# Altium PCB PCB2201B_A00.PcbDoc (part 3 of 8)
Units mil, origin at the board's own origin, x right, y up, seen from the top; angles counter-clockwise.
Board outline 4523.63 x 2358.23 mil, 6 copper layers (Top Layer, Signal Layer 2, Signal Layer 3, Signal Layer 4, Signal Layer 5, Bottom Layer), stack 61.221 mil thick; 383 components, 308 nets, 1386 pads, 1147 vias.
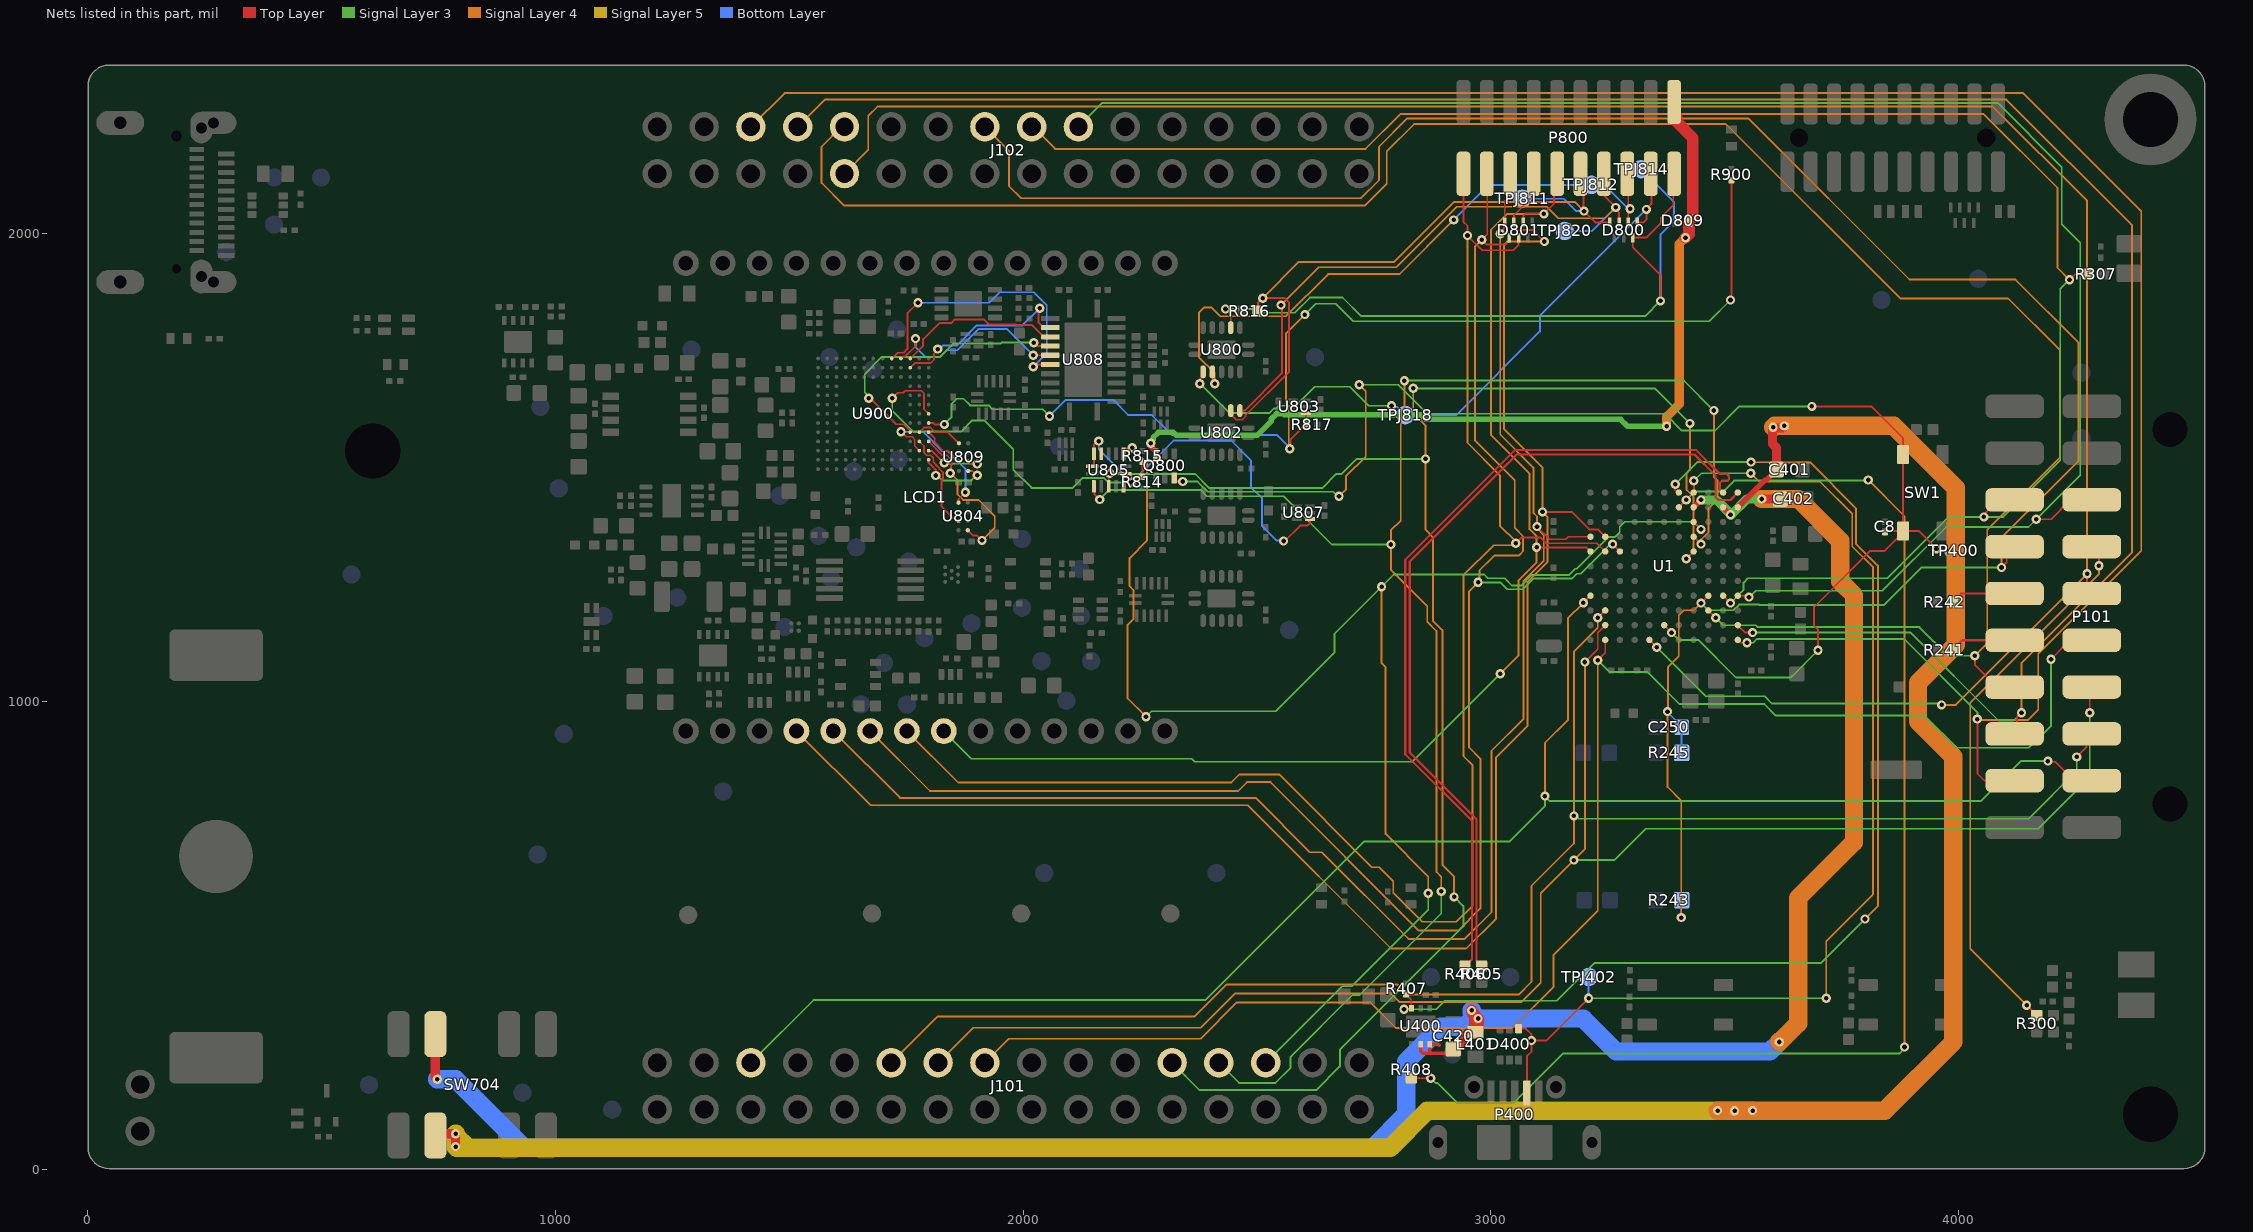
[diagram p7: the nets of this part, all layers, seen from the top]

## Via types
v1: diameter 19.68, hole 9.84, Top Layer to Bottom Layer, tented both sides, 768 vias
v2: diameter 20, hole 9.84, Top Layer to Bottom Layer, tented both sides, 379 vias

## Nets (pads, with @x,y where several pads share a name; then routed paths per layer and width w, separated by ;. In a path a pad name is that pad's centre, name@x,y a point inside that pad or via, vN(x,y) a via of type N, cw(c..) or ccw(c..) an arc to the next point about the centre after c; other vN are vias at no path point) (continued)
DEBUG_#RESET_C2CKPS: C8.1 Q800.6 SW1.1 SW1.2 TP400.1 U1.K6 | length 3010.6
  Top Layer w3.94: Q800.6@2322.83,1478.35 2322.83,1474.41 2326.77,1470.47 v2(2341.54,1470.47) ; U1.K6@3370.08,1163.39 v1(3385.85,1147.59) ; v1(3685.75,1630.98) 3812.59,1630.98 3880.58,1562.99 SW1.2@3880.58,1528.1 SW1.1@3880.58,1364.71 ; v1(3698.86,1109.76) 3698.86,1154.06 3690.35,1162.56 3690.35,1202.17 3810.2,1322.01 3841.16,1322.01 SW1.1@3881.93,1362.77 ; C8.1@3842.56,1362.77 3844.5,1364.71 SW1.1@3880.58,1364.71 ; SW1.1@3883.09,1362.2 SW1.1@3880.58,1364.71 ; v1(3952.2,1326.61) 3914.1,1364.71 3881.93,1364.71 SW1.1@3880.58,1364.71
  Signal Layer 3 w3.94: v2(2341.54,1470.47) 2372.5,1470.47 2394.38,1448.6 2662.55,1448.6 2672.17,1438.98 v1(2675.2,1438.98) ; v1@2718.94,1677.17 2802.06,1677.17 2864.06,1615.16 3372.05,1615.16 3408.03,1579.18 3478.78,1579.18 3530.59,1630.98 v1(3685.75,1630.98) ; v1(3385.85,1147.59) 3401.6,1131.85 3442.96,1131.85 3523.62,1051.18 3524.06,1051.62 3641.28,1051.62 3643.58,1053.92 3643.58,1054.49 v1(3698.86,1109.76)
  Signal Layer 4 w3.94: v1(2675.2,1438.98) 2690.37,1454.15 2690.37,1458.45 2690,1458.82 2690,1481.34 2732.28,1523.62 2732.28,1663.39 v1(2718.5,1677.17)
  Bottom Layer w3.94: v1(3952.2,1326.61) 3954.11,1324.71 3986.74,1324.71 TP400.1@3988.65,1322.8
DEBUG_#RESET_IN: U808.7 U900.N5 | length 628.1
  Top Layer w3.94: U900.N5@1719.49,1733.27 1731.93,1745.71 1744.93,1745.71 1752.95,1753.73 1752.95,1829.72 v2(1775.59,1852.36) ; v2(2021.65,1715.55) 2026,1715.55 2030.92,1720.47 U808.7@2058.27,1720.47
  Bottom Layer w3.94: v2(1775.59,1852.36) 1928.15,1852.36 1950.54,1874.75 2023,1874.75 2050.86,1846.89 2050.86,1744.75 v2(2021.65,1715.55)
DEBUG_DH_SW_ENABLE: R817.2 R900.1 U803.4 U900.F1 | length 2494.9
  Top Layer w3.94: U900.F1@1798.23,1595.47 1808.52,1595.47 1811.47,1592.52 v1(1832.06,1592.52) ; v2(2570.12,1540.35) 2571.85,1542.09 2571.85,1560.48 2595.96,1584.58 2597.33,1584.58 2604.73,1591.98 R817.2@2605.13,1591.98 2605.13,1615.34 U803.4@2604.33,1616.14 ; v1(3511.92,1858.27) 3513.78,1860.13 R900.1@3513.78,2114.17
  Signal Layer 3 w3.94: v1(1832.06,1592.52) 1846.91,1607.37 1846.91,1635.52 1858.75,1647.36 1872.79,1647.36 1887.02,1633.13 1926.38,1633.13 1934.65,1624.85 2041.91,1624.85 v2(2056.53,1610.24) ; v1(2602.36,1827.05) 2625.7,1850.39 2668.39,1850.39 2705.79,1812.99 3466.65,1812.99 v1(3511.92,1858.27)
  Signal Layer 4 w3.94: 2562.01,1652.59 2562.01,1637.8 2567.77,1632.03 2567.77,1542.7 v2(2570.12,1540.35) ; 2562.03,1652.61 2562.03,1667.37 2561.87,1667.53 2561.87,1786.56 v1(2602.36,1827.05)
  Bottom Layer w3.94: v2(2056.53,1610.24) 2090.98,1644.69 2192.38,1644.69 2224.58,1612.48 2275.31,1612.48 2317.91,1569.88 2542.32,1569.88 2570.12,1542.09 v2(2570.12,1540.35)
DEBUG_MCU_SW_ENABLE: R814.2 R815.2 U805.5 U805.6 U805.12 U805.13 U807.4 U900.G1 | length 1685.9
  Top Layer w3.94: v2(1720.47,1648.62) 1732,1660.15 1743.92,1660.15 1748.14,1664.37 1782.62,1664.37 1788.39,1658.6 1788.39,1625 U900.G1@1798.23,1615.16 ; U805.13@2148.23,1502.76 2149.61,1502.76 2151.57,1504.72 2151.57,1548.6 2159.82,1556.84 v2(2161.7,1556.84) ; U805.5@2214.57,1460.04 2214.57,1485.04 2216.54,1487.01 2227.36,1487.01 2229.78,1484.59 2229.98,1484.59 2232.28,1482.28 v2(2232.28,1468.5) 2244.11,1480.33 R814.2@2254.09,1480.33 ; R814.2@2254.92,1480.33 R815.2@2254.92,1512.03 ; v1(2556.85,1343.27) 2559.49,1343.27 2592.29,1376.07 2607.27,1376.07 2613.38,1382.17 U807.4@2613.38,1390.14
  Signal Layer 3 w3.94: v2(1720.47,1648.62) 1720.47,1621.83 1765.09,1577.21 1867.65,1577.21 1891.54,1601.1 1916.84,1601.1 1979.05,1538.89 1979.05,1495.87 2018.27,1456.65 2105.88,1456.65 2127.29,1478.07 2172.83,1478.07 2182.4,1468.5 v2(2232.28,1468.5)
  Bottom Layer w3.94: v2(2161.7,1556.84) 2161.7,1539.09 v2(2232.28,1468.5) 2321.77,1557.99 2444.88,1557.99 2486.92,1515.95 2486.92,1458.19 2510.79,1434.33 2510.79,1374.95 2541.1,1344.64 2555.48,1344.64 v1(2556.85,1343.27)
DEBUG_RESET_#OE: U804.A1 U900.D1 | length 347.2
  Top Layer w3.94: U900.D1@1799.48,1555.84 1799.48,1554.85 1827.78,1526.55 1837.53,1526.55 1847,1517.08 1847,1504.26 1845.97,1503.22 1845.97,1489.53 v2(1844.63,1488.19) ; U804.A1@1881.89,1366.14 1893.23,1354.8 1902.04,1354.8 1912.35,1344.49 v2(1912.4,1344.49)
  Signal Layer 4 w3.94: v2(1844.63,1488.19) 1860.23,1472.6 1860.23,1442.64 1871.97,1430.9 1904.95,1430.9 1939.68,1396.17 1939.68,1371.77 v2(1912.4,1344.49)
DEBUG_TCK_SWCLK_#OE: U809.A1 U900.B1 | length 161.3
  Top Layer w3.94: U900.B1@1798.23,1516.73 1798.37,1516.59 1798.37,1510.83 1813.7,1495.5 v2(1813.7,1483.18) ; U809.A1@1882.87,1493.11 1891.73,1493.11 1901.02,1483.83 v2(1902.13,1483.83)
  Signal Layer 3 w3.94: v2(1813.7,1483.18) 1813.7,1481.72 1818.04,1481.72 1827.03,1472.73 1889.62,1472.73 1900.16,1483.27 1901.57,1483.27 v2(1902.13,1483.83)
DEBUG_TCK_SWCLK_C2CK: J101.24 U1.E8 U805.3 | length 3693.5
  Top Layer w3.94: U805.3@2183.07,1460.04 2183.07,1486.22 v2(2185.04,1488.19) ; v1@3419.3,1307.09 U1.E8@3433.07,1320.87
  Signal Layer 3 w3.94: v2(2185.04,1488.19) 2186.73,1486.5 2367.61,1486.5 2397.64,1456.47 2639.19,1456.47 2669.41,1486.7 2681.15,1486.7 2713.11,1518.66 v1(2860.16,1518.66) ; J101.24@2318.5,228.43 2377.12,169.81 2626.51,169.81 2677.17,220.47 2677.17,255.91 2940.94,519.69 2940.94,562.99 v1(2921.26,582.68) ; v1(2833.97,1669.5) 3350.18,1669.5 v1(3425.2,1594.49)
  Signal Layer 4 w3.94: v1(2833.97,1669.5) 2833.97,1615.83 2860.16,1589.65 2860.16,1367.2 2875.98,1351.38 2875.98,1173.23 2896.19,1153.03 2896.19,651.06 2921.26,625.98 v1(2921.26,582.68) ; v1@3419.3,1307.09 3433.07,1320.86 3433.07,1437.01 3432.85,1437.23 3432.85,1437.51 3418.07,1452.3 3418.07,1488.19 3425.2,1495.32 v1(3425.2,1594.49)
  other v1: 3417.32,1305.12
DEBUG_TCK_SWCLK_IN: U808.4 U900.N3 | length 357.5
  Top Layer w3.94: U900.N3@1758.86,1733.27 1786.42,1760.83 1786.42,1774.61 1820.87,1809.06 1846.46,1809.06 1854.14,1816.74 1915.76,1816.74 1926.4,1806.1 1984.56,1806.1 1985.54,1805.12 2018.7,1805.12 2044.29,1779.53 U808.4@2058.27,1779.53
DEBUG_TCK_SWCLK_OUT: U809.B1 U900.C1 | length 140.5
  Top Layer w3.94: U900.C1@1798.23,1536.42 1798.98,1535.66 1804.89,1535.66 1830.5,1510.05 1831.11,1510.67 v2(1831.54,1510.67) ; U809.B1@1882.87,1512.8 1887.8,1507.87 v2(1902.56,1507.87)
  Signal Layer 3 w3.94: v2(1831.54,1510.67) 1830.5,1509.63 1831.38,1508.75 1901.68,1508.75 v2(1902.56,1507.87)
DEBUG_TDI_#OE: U809.B2 U900.E1 | length 96.1
  Top Layer w3.94: U900.E1@1798.23,1575.79 1811.3,1562.71 1811.3,1554.16 1830.03,1535.43 1840.55,1535.43 U809.B2@1863.19,1512.8
DEBUG_TDI_C2DPS: U805.11
DEBUG_TDI_IN: U808.6 U900.N4 | length 420.9
  Top Layer w3.94: U900.N4@1739.17,1733.27 1740.24,1733.27 1744.81,1737.84 1748.19,1737.84 1770.33,1759.98 v2(1770.33,1775.87) ; v2(2021.65,1740.16) U808.6@2058.27,1740.16
  Bottom Layer w3.94: v2(1770.33,1775.87) 1770.33,1757.23 1790.92,1736.64 1822.71,1736.64 1837.06,1750.98 1859.56,1750.98 1904.57,1795.99 1965.82,1795.99 v2(2021.65,1740.16)
DEBUG_TDI_OUT: U809.D2 U900.E2 | length 102.6
  Top Layer w3.94: U900.E2@1778.54,1575.79 1788.39,1585.63 1802.31,1585.63 1812.15,1575.79 1839.42,1575.79 1863.04,1552.17 U809.D2@1863.19,1552.17
DEBUG_TDO_SWO: J101.28 U1.C8 U805.8 | length 3309.6
  Top Layer w3.94: U805.8@2214.57,1529.72 2214.57,1538.39 2216.54,1540.35 2216.54,1541.14 2232.09,1541.14 v2(2233.27,1542.32) ; U1.C8@3433.07,1383.86 v1(3448.85,1368.09)
  Signal Layer 3 w3.94: v1(2262.8,967.52) 2274.61,979.33 2540.35,979.33 2665.35,1104.33 2665.35,1144.57 2792.44,1271.65 2985.24,1271.65 2993.11,1263.78 3029.22,1263.78 3044.97,1248.03 3064.65,1248.03 3087.4,1270.78 3167.43,1270.78 3180.56,1283.9 3183.51,1283.9 3251.51,1351.91 3265.35,1351.91 3275.2,1361.76 3275.2,1373.69 3285.79,1384.28 3432.66,1384.28 v1(3448.85,1368.09) ; J101.28@2518.5,228.43 2681.81,391.73 2702.76,391.73 2866.14,555.12 v1(2866.14,590.55)
  Signal Layer 4 w3.94: v2(2233.27,1542.32) 2264.76,1510.83 2264.76,1343.83 2227.64,1306.71 2227.64,1246.85 2235.94,1238.56 2235.94,1176.25 2223.58,1163.89 2223.58,1006.74 2261.81,968.5 v1@2261.81,967.52 ; v1(2766.26,1245.47) 2766.26,1082.13 2774.76,1073.62 2774.76,717.36 2866.14,625.98 v1(2866.14,590.55)
DEBUG_TDO_SWO_IN: U808.5 U900.E3 | length 603.6
  Top Layer w3.94: v2(1670.28,1648.62) 1673.45,1648.62 1729.27,1592.8 1745.2,1592.8 1754.74,1583.26 1758.11,1579.89 1758.11,1576.54 U900.E3@1758.86,1575.79 ; v2(2022.64,1766.73) 2025.98,1766.73 2032.87,1759.84 U808.5@2058.27,1759.84
  Signal Layer 3 w3.94: v2(1670.28,1648.62) 1670.28,1652.97 1661.7,1661.55 1661.7,1700.08 1698.25,1736.64 1822.71,1736.64 1851.12,1765.05 1951.8,1765.05 1954.55,1767.81 2021.56,1767.81 v2(2022.64,1766.73)
DEBUG_TMS_SWDIO_#OE: U804.B2 U900.D2 | length 215.3
  Top Layer w3.94: U900.D2@1778.54,1556.1 1788.39,1546.26 1788.39,1532.34 1794.15,1526.57 1802.31,1526.57 1808.07,1520.81 1808.07,1512.26 1815.94,1504.39 1821.57,1498.76 1821.57,1497.19 1829.17,1489.59 1829.17,1488.12 1829.17,1475.31 1826.07,1472.21 1826.07,1416.82 1856.19,1386.69 1861.34,1386.69 U804.B2@1862.2,1385.83
DEBUG_TMS_SWDIO_C2D: J101.26 U1.D8 U805.1 | length 3578.5
  Top Layer w3.94: U805.1@2151.57,1460.04 2152.45,1459.17 2152.45,1443.57 v2(2164.21,1431.81) ; U1.D8@3433.07,1352.36 v1(3448.85,1336.59)
  Signal Layer 3 w3.94: v2(2164.21,1431.81) 2164.21,1432.67 2184.01,1452.48 2379.36,1452.48 2392.86,1438.98 2556.81,1438.98 2659.96,1335.83 v1(2786.1,1335.83) ; J101.26@2418.5,228.43 2461.89,185.04 2539.37,185.04 2571.85,217.52 2571.85,241.14 2703.74,373.03 2719.49,373.03 2893.7,547.24 v1(2893.7,594.49) ; v1(2814.96,1685.91) 3412.51,1685.91 v1(3476.38,1622.05)
  Signal Layer 4 w3.94: v1(2814.96,1685.91) 2814.96,1614.17 2807.09,1606.3 2807.09,1386.81 2786.1,1365.83 v1(2786.1,1335.83) 2786.1,1281.61 2863.7,1204.02 2863.7,1170.71 2883.62,1150.79 2883.62,636.07 2893.7,625.98 v1(2893.7,594.49) ; v1(3448.85,1336.59) 3448.85,1346.17 3465.04,1362.36 3465.04,1413.68 3484.25,1432.89 3484.25,1472.32 3476.38,1480.19 v1(3476.38,1622.05)
DEBUG_TMS_SWDIO_IN: U808.3 U900.M3 | length 398.7
  Top Layer w3.94: U900.M3@1758.86,1713.58 1768.7,1723.43 1802.31,1723.43 1809.73,1730.85 1809.73,1743.1 1817.64,1751.01 v2(1817.64,1753.44) ; v2(2035.39,1840.49) 2032.87,1837.97 2032.87,1810.63 2044.29,1799.21 U808.3@2058.27,1799.21
  Bottom Layer w3.94: v2(1817.64,1753.44) 1820.67,1753.44 1828.06,1760.83 1858.27,1760.83 1901.3,1803.86 1998.77,1803.86 v2(2035.39,1840.49)
DEBUG_TMS_SWDIO_OUT: U804.D2 U900.C2 | length 308.4
  Top Layer w3.94: v2@1743.11,1573.82 1743.11,1573.69 1750.86,1565.94 1762.94,1565.94 1768.7,1560.18 1768.7,1546.26 U900.C2@1778.54,1536.42 ; U804.D2@1862.2,1425.2 1862.2,1433.07 v2(1876.94,1447.81)
  Bottom Layer w3.94: v2(1739.27,1576.85) 1786.34,1576.85 1827.76,1535.43 1839.57,1535.43 1876.94,1498.06 v2(1876.94,1447.81)
DEBUG_TRACECLK: D801.2 LCD1.8 P800.12 U1.E1 | length 2713.3
  Top Layer w3.94: D801.2@3068.9,2024.21 3069.09,2024.4 3069.09,2038.24 3074.16,2043.31 3114.17,2043.31 3134.68,2063.82 3134.68,2118.6 P800.12@3139.62,2123.53 ; v1(3097.44,1329.72) 3203.74,1329.72 U1.E1@3212.6,1320.87
  Signal Layer 3 w3.94: LCD1.8@1830.71,937.01 1889.76,877.95 2360.55,877.95 2367,871.5 2831.69,871.5 v1(3019.68,1059.49)
  Signal Layer 4 w3.94: v1(3019.68,1059.49) 3059.06,1098.86 3059.06,1259.17 3097.44,1297.55 v1(3097.44,1329.72) 3097.44,1353.35 3082.68,1368.11 3082.68,1487.2 3000,1569.88 3000,2007.87 3034.45,2042.32 v1(3113.19,2042.32)
DEBUG_TRACED0: D801.3 LCD1.4 P800.14 U1.D2 | length 3679
  Top Layer w3.94: D801.3@3049.21,2024.21 3049.21,2039.64 3091.14,2081.57 P800.14@3091.14,2124.72 ; D801.3@3050.2,2016.54 3058.86,2007.87 3089.57,2007.87 v1(3114.17,1983.27) ; v1(3110.24,1405.51) 3172.72,1405.51 3210.13,1368.09 3228.36,1368.09 U1.D2@3244.09,1352.36
  Signal Layer 4 w3.94: LCD1.4@1515.75,937.01 1674.21,778.54 2480.32,778.54 2786.42,472.44 2946.85,472.44 3010.83,536.42 3010.83,880.91 3077.76,947.83 3077.76,1254.92 3120.63,1297.79 3120.63,1395.12 v1(3110.24,1405.51) 3110.24,1500 3027.56,1582.68 3027.56,1976.38 3034.45,1983.27 v1(3114.17,1983.27)
DEBUG_TRACED1: D801.4 LCD1.5 P800.16 U1.D1 | length 3395
  Top Layer w3.94: v1@3016.73,2000 3028.13,2011.4 3028.13,2022.81 D801.4@3029.53,2024.21 3029.53,2069.56 3044.29,2084.32 P800.16@3044.29,2107.28 ; v1(3098.43,1374.02) 3125.55,1346.89 3160.15,1346.89 3165.62,1352.36 U1.D1@3212.6,1352.36
  Signal Layer 4 w3.94: LCD1.5@1594.49,937.01 1737.2,794.29 2497.05,794.29 2613.19,678.15 2638.78,678.15 2823.82,493.11 2943.9,493.11 3001.11,550.32 3001.11,894.81 3069.88,963.58 3069.88,1258.18 3112.75,1301.05 3112.75,1355.86 3098.43,1370.19 3098.43,1395.67 3090.55,1403.54 3090.55,1500 3019.68,1570.87 v1(3019.68,2000)
DEBUG_TRACED2: D801.5 LCD1.6 P800.18 U1.E3 | length 3649.5
  Top Layer w3.94: P800.18@2991.14,2124.72 2992.13,2123.74 2992.13,1999.02 v1(2980.32,1987.2) 2990.9,1976.62 3030.76,1976.62 3037.2,1983.07 3037.6,1983.07 3040.55,1986.02 D801.5@3040.55,1986.42 ; v1(3259.85,1336.59) U1.E3@3275.59,1320.87
  Signal Layer 3 w3.94: v1(2972.44,1254.92) 3020.29,1254.92 3035.06,1240.16 3067.91,1240.16 3090.66,1262.91 3172.79,1262.91 3183.07,1273.19 3191.49,1273.19 3254.9,1336.59 v1(3259.85,1336.59)
  Signal Layer 4 w3.94: LCD1.6@1673.23,937.01 1801.18,809.06 2459.65,809.06 2478.89,828.3 2528.63,828.3 2846.1,510.83 2930.12,510.83 2977.36,558.07 2977.36,877.76 2953.19,901.93 2953.19,1235.67 v1(2972.44,1254.92) 2975.15,1257.63 2975.15,1280.27 3006.89,1312.01 3059.06,1312.01 3068.46,1321.41 3068.46,1353.47 3050.74,1371.19 3050.74,1472.88 2965.99,1557.63 2965.99,1972.88 v1(2980.32,1987.2)
DEBUG_TRACED3: D801.6 LCD1.7 P800.20 U1.E2 | length 3458
  Top Layer w3.94: P800.20@2941.14,2124.72 2941.14,2025.39 2949.8,2016.73 v1(2949.8,1996.06) 2981.3,1964.57 3047.24,1964.57 3059.06,1976.38 D801.6@3059.06,1991.54 ; v1(3053.15,1338.58) 3064.96,1350.39 3106.3,1350.39 3118.11,1338.58 3226.38,1338.58 U1.E2@3244.09,1320.87
  Signal Layer 4 w3.94: LCD1.7@1751.97,937.01 1861.77,827.21 2445.32,827.21 2462.6,844.49 2547.24,844.49 2745.57,646.16 2761.32,646.16 2791.34,616.14 2791.34,591.54 2853.35,529.53 2926.18,529.53 2960.63,563.98 2960.63,864.17 2940.94,883.86 2940.94,1269.69 3005.49,1334.23 3048.8,1334.23 v1(3053.15,1338.58) 3053.15,1342.41 3019.25,1376.31 3019.25,1483.7 2949.8,1553.15 v1(2949.8,1996.06)
DH_#RESET: D800.4 P800.10 R816.1 TPJ811.1 U802.3 | length 1490.3
  Top Layer w3.94: U802.3@2443.9,1622.05 2443.9,1614.17 2455.71,1602.36 2468.47,1602.36 2475.39,1609.28 2475.39,1612.2 2568.46,1705.27 2568.46,1852.8 2559.05,1862.2 2558.07,1862.2 2557.56,1862.72 2512.62,1862.72 v1(2512.11,1862.2) ; R816.1@2500.98,1834.65 2501.97,1835.63 2501.97,1852.36 v1@2511.81,1862.2 ; P800.10@3189.62,2125.5 3197.72,2117.4 3197.72,2049.33 v1(3198.82,2048.23) 3222.83,2024.21 D800.4@3253.94,2024.21
  Signal Layer 4 w3.94: v1(2512.11,1862.2) 2589.51,1939.61 2792.95,1939.61 2921.26,2067.91 3179.13,2067.91 v1(3198.82,2048.23)
  Bottom Layer w3.94: TPJ811.1@3067.71,2074.8 3155.51,2074.8 3182.09,2048.23 v1(3198.82,2048.23)
DH_TCK_SWCLK: D800.1 P800.4 TPJ818.1 U800.9 | length 1378.4
  Top Layer w3.94: v2(2377.95,1679.13) 2377.95,1688.98 2384.84,1695.87 U800.9@2384.84,1704.72 ; D800.1@3314.76,2023.62 3325.79,2023.62 3332.13,2029.96 3332.13,2052.92 3342.77,2063.56 3342.77,2123.3 P800.4@3341.34,2124.72
  Signal Layer 3 w3.94: v2(2377.95,1679.13) 2379.16,1679.13 2441.81,1616.48 2526.3,1616.48 2536.35,1626.53 2540.93,1626.53 2546.84,1632.44 2583.22,1632.44 2623.58,1672.79 2698.27,1672.79 2738.63,1632.44 v1(2787.4,1632.44)
  Bottom Layer w3.94: v1(2787.4,1632.44) 2789.54,1630.3 2798.83,1630.3 TPJ818.1@2816.93,1612.2 2852.36,1612.2 2925.71,1612.2 3104.65,1791.14 3104.65,1824.45 v1(3332.13,2051.93)
DH_TDI: D800.3 P800.8 TPJ820.1 U802.2 | length 1336.2
  Top Layer w3.94: U802.2@2463.58,1622.05 2473.65,1622.05 2553.15,1701.55 2553.15,1846.46 2552.17,1846.46 v1(2551.22,1847.41) ; P800.8@3241.14,2124.72 3241.14,2081.69 v1(3266.73,2056.1) 3266.73,2051.84 3273.62,2044.95 D800.3@3273.62,2024.21
  Signal Layer 4 w3.94: v1(2551.22,1847.41) 2632.08,1928.27 2797.36,1928.27 2926.73,2057.63 3119.53,2057.63 3144.25,2032.92 3243.55,2032.92 v1(3266.73,2056.1)
  Bottom Layer w3.94: TPJ820.1@3157.48,2005.91 3216.54,2005.91 v1(3266.73,2056.1)
DH_TDO_SWO: D800.2 P800.6 TPJ812.1 U800.10 | length 1379.7
  Top Layer w3.94: v2@2404.53,1682.09 2406.37,1683.93 2406.37,1686.55 2406.03,1686.89 2406.03,1703.22 U800.10@2404.53,1704.72 ; P800.6@3289.62,2125.5 3293.31,2121.81 v1@3293.31,2053.15 ; D800.2@3293.31,2018.69 v1@3293.31,2053.15 ; v1(3297.35,2053.15) v1@3293.31,2053.15
  Signal Layer 4 w3.94: v2(2409.45,1679.13) 2409.45,1702.76 2375.98,1736.22 2375.98,1830.71 2387.64,1842.36 2402.72,1842.36 2421.43,1823.65 2561.84,1823.65 2651.93,1913.74 2804.49,1913.74 v1(2920.28,2029.53)
  Bottom Layer w3.94: v1@2915.85,2025.1 v1(2920.28,2029.53) 2995.08,2104.33 TPJ812.1@3214.57,2104.33 3216.86,2102.04 3244.42,2102.04 3293.31,2053.15 v1(3297.35,2053.15)
DH_TMS_SWDIO: D800.7 P800.2 TPJ814.1 U800.3 | length 1689.5
  Top Layer w3.94: v2(2432.62,1839.12) 2443.9,1827.85 U800.3@2443.9,1799.21 ; v1(3362.2,1856.3) 3362.2,1912.4 3303.15,1971.46 3303.15,1990.35 3304.92,1992.13 3332.68,1992.13 3363.19,2022.64 3363.19,2034.64 3389.62,2061.07 P800.2@3389.62,2125.5
  Signal Layer 3 w3.94: v2(2432.62,1839.12) 2504.92,1839.12 2512.89,1831.15 2580.84,1831.15 2613.35,1863.66 2682.76,1863.66 2722.53,1823.89 3329.79,1823.89 v1(3362.2,1856.3)
  Bottom Layer w3.94: TPJ814.1@3320.87,2137.8 3391.5,2067.17 3391.5,2027.36 3362.2,1998.07 v1(3362.2,1856.3)
DH_VTREF: D809.1 P800.1 Q800.3 | length 1877.6
  Top Layer w11.81: v2(2272.64,1552.17) 2274.2,1550.6 2274.2,1544.69 2283.46,1535.43 Q800.3@2283.46,1529.53
  Top Layer w25: P800.1@3396.65,2251.97 3396.65,2238.91 3431.1,2204.46 3431.1,2035.43 D809.1@3424.51,2028.84 ; v1(3415.78,1991.45) 3423.23,1998.91 D809.1@3423.23,2027.56
  Signal Layer 3 w11.81: v2(2272.64,1552.17) 2272.64,1554.38 2277.84,1559.58 2277.84,1564.14 2289.21,1575.51 2321.26,1575.51 2327.59,1569.18 2500.28,1569.18 2529.96,1598.86 2529.96,1603.45 2541.24,1614.72 2557.19,1614.72 2558.72,1613.19 2849.33,1613.19 2859.17,1603.35 3277.09,1603.35 3291.97,1588.46 v1(3375.35,1588.46)
  Signal Layer 4 w19.68: v1(3375.35,1588.46) 3375.35,1608.62 3402.56,1635.83 3402.56,1978.24 v1(3415.78,1991.45)
EFM_USB_DM: R406.2 U1.A10 | length 1797.6
  Top Layer w4.72: R406.2@2944.88,435.04 2959.37,449.53 2959.37,745.16 2816.93,887.6 2816.93,1303.48 3050.89,1537.44 3438.69,1537.44 3489.59,1486.54 3504.21,1486.54 3508.58,1482.17 3508.58,1475.01 3505.82,1472.24 3494.08,1472.24 3489.59,1467.76 3489.59,1454.15 3496.06,1447.68 U1.A10@3496.06,1446.85
EFM_USB_DP: R405.2 U1.A11 | length 1797.6
  Top Layer w4.72: R405.2@2980.31,435.04 2968.82,446.54 2968.82,749.07 2826.38,891.51 2826.38,1299.57 3054.8,1527.99 3434.78,1527.99 3480.06,1482.7 3480.06,1436.98 3486.02,1431.03 3511.74,1431.03 U1.A11@3527.56,1446.85
EFM_USB_ID: D400.1 P400.4 TPJ402.1 U1.A8 | length 2376.5
  Top Layer w3.94: D400.1@3059.05,301.18 3074.61,301.18 3086.61,289.17 v1(3086.61,275.59) ; P400.4@3076.57,163.39 P400.4@3076.57,163.66 ; P400.4@3076.79,163.66 3076.79,242.14 3086.61,251.97 v1(3086.61,275.59) ; v1(3208.66,366.14) 3118.11,275.59 v1(3086.61,275.59) ; U1.A8@3433.07,1446.85 3433.57,1447.37 v1(3433.57,1471.88)
  Signal Layer 3 w3.94: v1(3208.66,366.14) v1(3716.54,366.14) ; v1(3433.57,1471.88) 3449.88,1488.19 v1(3555.12,1488.19)
  Signal Layer 4 w3.94: v1(3555.12,1488.19) 3573.19,1470.12 3703.11,1470.12 3771.93,1401.3 3771.93,1331.5 3816.5,1286.93 3816.5,588.15 3716.54,488.19 v1(3716.54,366.14)
  Bottom Layer w3.94: v1(3208.66,366.14) TPJ402.1@3208.66,411.42
EFM_USB_OC_FAULT: R408.1 U1.B7 | length 2800.4
  Top Layer w3.94: U1.B7@3401.6,1415.35 v1(3417.35,1431.09)
  Top Layer w4: R408.1@2829.68,195.59 2830.04,195.24 v1(2871.14,195.24)
  Signal Layer 3 w4: v1(2871.14,195.24) 2881.12,185.26 2885.61,185.26 2929.13,141.73 3047.24,141.73 3153.54,248.03 3872.42,248.03 3883.73,259.34 v1(3883.73,261.96) ; v1(3417.35,1431.09) 3435.07,1448.82 3496.06,1448.82 3519.68,1472.44 3804.92,1472.44 v1(3806.2,1473.72)
  Signal Layer 4 w4: v1(3806.2,1473.72) 3883.73,1396.18 v1(3883.73,261.96)
EFM_USB_VBUS: C402.1 C420.1 L401.2 SW704.6 U1.B8 U1.B10 U400.5 U400.6 | length 5160.5
  Top Layer w7.87: U400.5@2849.88,267.76 2849.88,253 2854.49,248.39 2864.76,248.39 ; 2889.06,266.02 2887.32,267.76 U400.6@2869.57,267.76 2869.37,267.56 2869.37,253 2864.76,248.39 ; C420.1@2919.33,257.68 2910.04,248.39 2864.76,248.39
  Top Layer w11.81: v1@2958.66,336.61 2958.66,300.98 2965.94,293.7 L401.2@2967.17,293.7 ; 2971.99,309.68 v1@2971.99,322.38 ; U1.B8@3433.11,1415.35 v1(3448.85,1431.09) ; U1.B10@3496.06,1415.35 v1(3511.85,1399.59)
  Top Layer w19.68: SW704.6@744.09,285.43 744.09,196.85 v1(748.03,192.91) ; v1(3578.74,1433.07) C402.1@3614.17,1433.07
  Top Layer w25: C420.1@2919.33,257.68 2920.31,257.68 2955.65,293.01 L401.2@2965.26,293.01 ; v1(2958.66,340.25) 2958.66,336.61 v1(2972.44,322.83) ; L401.2@2965.94,293.7 L401.2@2965.26,293.01 ; L401.2@2967.17,293.7 L401.2@2971.3,293.7 ; v1@2971.99,322.38 v1(2972.44,322.83) ; L401.2@2965.26,293.01 2970.61,293.01 L401.2@2971.3,293.7 ; L401.2@2971.3,293.7 2971.99,294.39 2971.99,299.74 2972.44,300.2 v1(2972.44,322.83)
  Signal Layer 3 w19.68: v1(3448.85,1431.09) 3481.86,1431.09 3511.85,1401.11 v1(3511.85,1399.59) 3513.77,1399.59 3547.24,1433.07 v1(3578.74,1433.07)
  Signal Layer 4 w39.37: v1(3578.74,1433.07) 3656.89,1433.07 3746.34,1343.62 3746.34,1256.99 3775.75,1227.58 3775.75,699.8 3656.34,580.39 3656.34,312.2 3616.87,272.73 v1(3616.28,272.73)
  Bottom Layer w39.37: v1(748.03,192.91) 787.4,192.91 933.07,47.24 2748.03,47.24 2818.9,118.11 2818.9,230.87 2893.11,305.08 2942.87,305.08 2960.63,322.83 ; v1(2958.66,340.25) 2958.66,336.61 v1(2972.44,322.83) 3196.85,322.83 3267.4,252.28 3595.84,252.28 v1(3616.28,272.73)
EFM_USB_VBUSEN: R407.2 U1.A7 U400.3 | length 2496
  Top Layer w3.94: v1(2814.09,342.64) 2828.31,342.64 U400.3@2830.2,344.53 2829.55,345.17 2829.55,363.24 2823.39,369.41 2822.99,369.41 2818.66,373.74 R407.2@2818.66,374.13 ; v1(3393.7,1464.57) 3393.7,1452.11 3398.96,1446.85 U1.A7@3401.57,1446.85 U1.A7@3402.56,1446.85 ; v1@3393.7,1465.55 v1@3394.19,1465.06
  Signal Layer 3 w3.94: v1(2814.09,342.64) 2814.21,342.52 2883.39,342.52 2901.58,360.71 3140.24,360.71 3220.91,441.38 3705.16,441.38 v1(3799.21,535.43) ; v1(3393.7,1464.57) 3440.94,1511.8 v1(3555.71,1511.8)
  Signal Layer 4 w3.94: v1(3555.71,1511.8) 3555.94,1511.57 3633.94,1511.57 3634.31,1511.2 3681.87,1511.2 3779.8,1413.27 3779.8,1337.8 3826.77,1290.83 3826.77,562.99 v1(3799.21,535.43)
EFM_USB_VREGO: C401.1 SW704.2 U1.B11 | length 5436.1
  Top Layer w11.81: U1.B11@3527.56,1415.35 3585.49,1473.29 3588.44,1473.29 3610.24,1495.08 C401.1@3610.24,1496.06
  Top Layer w19.68: SW704.2@744.09,76.77 v1(787.4,76.77) v1(787.4,49.21) ; v1(3603,1586.14) v1@3601.48,1584.62 ; C401.1@3610.24,1496.06 3610.24,1542.32 3601.48,1551.08 v1@3601.48,1584.62 ; v1(3626.58,1589.15) 3622.04,1584.62 v1@3601.48,1584.62
  Signal Layer 4 w39.37: v1(3484.25,125.98) 3484.43,125.81 v1(3520.63,125.81) 3520.81,125.98 v1(3559.05,125.98) 3841.5,125.98 3988.35,272.83 3988.35,882.28 3912.52,958.11 3912.52,1040.32 3993.31,1121.1 3993.31,1456.65 3860.79,1589.17 v1(3626.58,1589.15) ; v1(3603,1586.14) 3606.01,1589.15 v1(3626.58,1589.15)
  Signal Layer 5 w39.37: v1(787.4,76.77) v1@787.4,72.51 ; 811.18,48.73 v1@787.4,72.51 ; v1(3559.05,125.98) 3558.88,125.81 v1(3520.63,125.81) 3484.43,125.81 v1(3484.25,125.98) 2864.17,125.98 2784.73,46.54 790.07,46.54 v1(787.4,49.21) v1@787.4,72.51
EXP_HEADER3: J101.6 P101.3 U1.H1 | length 3629.5
  Top Layer w3.94: v1(3197.49,1211.24) U1.H1@3212.6,1226.38 ; v1(4190.14,872.85) 4191.3,871.69 4205.89,871.69 4246.48,831.1 P101.3@4273.91,831.1
  Signal Layer 3 w3.94: J101.6@1418.5,228.43 1552.28,362.2 2389.76,362.2 2728.35,700.79 3039.37,700.79 3115.34,776.76 v1(3115.34,798.05) 3125.98,787.4 4046.89,787.4 4132.34,872.85 v1(4190.14,872.85)
  Signal Layer 4 w3.94: v1(3115.34,798.05) 3115.34,911.6 3164.37,960.63 3164.37,1178.12 3196.85,1210.59 v1(3197.49,1211.24)
EXP_HEADER4: J102.6 P101.4 U1.L11 | length 5206.1
  Top Layer w3.94: U1.L11@3527.56,1131.89 U1.L11@3527.62,1131.89 ; U1.L11@3527.56,1131.95 U1.L11@3527.62,1131.89 ; v1(3547.24,1125.98) 3533.53,1125.98 U1.L11@3527.62,1131.89 ; v1(4039.37,962.6) 4039.37,846.46 4054.72,831.1 P101.4@4119.02,831.1 P101.4@4123.91,831.1
  Signal Layer 3 w3.94: v1(3547.24,1125.98) 3560.35,1125.98 3568.22,1133.86 3882.87,1133.86 4039.37,977.36 v1(4039.37,962.6)
  Signal Layer 4 w3.94: J102.6@1418.5,2228.43 1490.39,2300.32 4137.17,2300.32 4389.76,2047.72 4389.76,1322.32 4169.41,1101.97 4169.41,982.2 4148.27,961.07 4040.9,961.07 v1(4039.37,962.6)
EXP_HEADER5: J101.12 P101.5 U1.J2 | length 3538.6
  Top Layer w3.94: v1(3228.35,1179.09) U1.J2@3244.09,1194.88 ; v1@4252.95,882.87 4272.58,902.5 4272.58,929.78 P101.5@4273.91,931.1
  Signal Layer 3 w3.94: J101.12@1718.5,228.43 J101.12@1734.8,228.43 ; v1(3177.17,755.91) 3181.2,755.91 3187.35,749.76 4148.86,749.76 4251.97,852.87 v1(4251.97,881.89)
  Signal Layer 4 w3.94: J101.12@1718.5,228.43 1816.85,326.77 2366.14,326.77 2435.04,395.67 2800.2,395.67 2821.85,374.02 3059.05,374.02 3086.61,401.57 3086.61,606.3 3177.17,696.85 v1(3177.17,755.91) 3177.17,1106.3 3228.35,1157.48 v1(3228.35,1179.09)
EXP_HEADER6: J102.8 P101.6 U1.K11 | length 4873.2
  Top Layer w3.94: U1.K11@3527.56,1163.39 3543.34,1147.6 v1(3559.02,1147.6) ; P101.6@4123.91,931.1 4123.91,966.43 v1(4133.86,976.38)
  Signal Layer 3 w3.94: v1(3559.02,1147.6) 3896.69,1147.6 4084.65,959.65 4117.13,959.65 v1(4133.86,976.38)
  Signal Layer 4 w3.94: J102.8@1518.5,2228.43 1576.57,2286.5 4101.38,2286.5 4370.08,2017.8 4370.08,1318.9 4133.86,1082.68 v1(4133.86,976.38)
EXP_HEADER7: J101.14 P101.7 U1.K2 | length 3565.3
  Top Layer w3.94: v1(3200.75,1084.59) 3228.36,1112.2 3228.36,1147.65 U1.K2@3244.09,1163.39 ; P101.7@4273.91,1031.1 4279.53,1025.48 v1(4279.53,976.38)
  Signal Layer 3 w3.94: v1(3177.17,661.42) 3263.78,661.42 3330.71,728.35 4169.61,728.35 4279.53,838.27 v1(4279.53,976.38)
  Signal Layer 4 w3.94: J101.14@1818.5,228.43 1893.23,303.15 2379.92,303.15 2452.76,375.98 2786.76,375.98 2804.48,358.27 3065.35,358.27 3106.3,399.21 3106.3,590.55 v1(3177.17,661.42) 3200.75,685 v1(3200.75,1084.59)
EXP_HEADER8: J102.10 P101.8 U1.J9 | length 4590.6
  Top Layer w3.94: U1.J9@3464.57,1194.88 v1(3480.35,1179.09) ; v1(4034.06,1098.07) 4034.06,1078.4 4081.35,1031.1 P101.8@4123.91,1031.1
  Signal Layer 3 w3.94: v1(3480.35,1179.09) 3496.35,1163.09 3566.09,1163.08 3569.94,1159.22 3915.58,1159.22 3976.73,1098.07 v1(4034.06,1098.07)
  Signal Layer 4 w3.94: J102.10@1618.5,2228.43 1611.89,2228.43 1569.33,2185.87 1569.33,2108.62 1618.08,2059.87 2730.04,2059.87 2777.29,2107.12 2777.29,2175.99 2835.68,2234.38 3501.88,2234.38 3874.61,1861.65 4104.92,1861.65 4216.1,1750.48 4216.1,1522.48 4060.7,1367.08 4060.7,1124.72 v1(4034.06,1098.07)
EXP_HEADER9: J101.16 P101.9 U1.L2 | length 3419.6
  Top Layer w3.94: v1(3228.35,1088.59) v1(3228.35,1088.59) 3244.06,1104.3 U1.L2@3244.06,1131.95 ; v1@4195.87,1087.6 4195.87,1090.07 4236.9,1131.1 P101.9@4273.91,1131.1
  Signal Layer 3 w3.94: v1(3228.35,1088.59) 3253.95,1062.99 3334.65,1062.99 3402.66,994.98 3584.23,994.98 3609.05,970.16 3926.34,970.16 3994.92,901.57 4149.61,901.57 4196.85,948.82 v1(4196.85,1090.55)
  Signal Layer 4 w3.94: J101.16@1918.5,228.43 1969.61,279.53 2379.37,279.53 2457.13,357.28 2742.13,357.28 2796.89,302.52 3045.63,302.52 3133.86,390.75 3133.86,458.72 3228.35,553.21 v1(3228.35,1088.59)
EXP_HEADER10: P101.10 R241.2 | length 146.3
  Top Layer w5: R241.2@3986.22,1110.24 4007.09,1131.1 P101.10@4123.91,1131.1
EXP_HEADER11: J102.9 P101.11 U1.L5 | length 4788.8
  Top Layer w3.94: U1.L5@3338.58,1131.89 v1(3354.35,1116.09) ; P101.11@4273.91,1231.1 v1(4273.91,1273.34)
  Signal Layer 3 w3.94: v1(3354.35,1116.09) 3458.9,1011.54 3584.84,1011.54 3600.39,995.98 3959.91,995.98 v1(3962.92,992.97)
  Signal Layer 4 w3.94: J102.9@1618.5,2128.43 1669.29,2179.21 1669.29,2251.97 1689.01,2271.68 4072.25,2271.68 4273.91,2070.03 v1(4273.91,1273.34) 3993.54,992.97 v1(3962.92,992.97)
EXP_HEADER12: P101.12 R242.2 | length 145.3
  Top Layer w4: R242.2@3986.22,1212.6 4004.72,1231.1 P101.12@4123.91,1231.1
EXP_HEADER13: P101.13 R300.2 | length 1199.6
  Top Layer w3.94: v1(4144.68,351.38) R300.2@4166.34,329.72 ; P101.13@4273.91,1331.1 4299.21,1331.1 v1(4299.21,1290.35)
  Signal Layer 4 w3.94: v1(4144.68,351.38) 4114.17,381.89 4024.06,472 4024.06,997.48 4114.17,1087.6 4299.21,1272.64 v1(4299.21,1290.35)
EXP_HEADER14: C250.2 J102.16 P101.14 R243.2 R245.2 U1.H9 | length 4941
  Top Layer w3.94: v1(3448.85,1210.59) 3464.57,1226.31 U1.H9@3464.57,1226.38 ; v1(4091.1,1286.57) 4102.24,1297.71 4102.24,1309.44 P101.14@4123.91,1331.1
  Signal Layer 3 w3.94: v1(3448.85,1210.59) 3464.16,1195.28 3518.19,1195.28 3530.21,1207.3 3573.31,1207.3 3574.46,1206.14 3839.17,1206.14 3919.61,1286.57 v1(4091.1,1286.57)
  Signal Layer 4 w3.94: J102.16@1918.5,2228.43 1969.72,2177.2 1969.72,2101.89 1996.03,2075.59 2721.89,2075.59 2760.67,2114.37 2760.67,2185.67 2821.46,2246.46 3550.04,2246.46 3894.45,1902.05 4120.87,1902.05 4255.91,1767.01 4255.91,1514.8 4095.18,1354.07 4091.1,1350 v1(4091.1,1286.57) ; v1(3406.54,538.58) 3406.54,788.39 3377.22,817.71 v1(3377.22,978.67) 3378.39,979.85 3378.39,1074.18 3401.22,1097.01 3401.22,1184.62 3411.88,1195.28 3433.54,1195.28 v1(3448.85,1210.59)
  Bottom Layer w3.94: v1(3377.22,978.67) 3377.22,977.35 3407.52,947.05 R245.2@3407.52,890.43 R245.2@3410.13,887.82 ; v1(3406.54,538.58) 3406.54,574.8 R243.2@3407.52,575.79
EXP_HEADER15: J102.20 P101.15 U1.H11 | length 3820.8
  Top Layer w3.94: U1.H11@3527.56,1226.38 3548.46,1226.38 v1(3551.35,1223.48) ; v1(4165.35,1389.76) 4196.85,1389.76 4238.19,1431.1 P101.15@4273.91,1431.1
  Signal Layer 3 w3.94: J102.20@2118.5,2228.43 2169.61,2279.53 4082.68,2279.53 4219.82,2142.38 4219.82,2020.32 4259.41,1980.74 4259.41,1483.82 v1(4165.35,1389.76) 4148.74,1373.15 3972.52,1373.15 3836.2,1236.83 3565.57,1236.83 3552.22,1223.48 v1(3551.35,1223.48)
EXP_HEADER16: J102.18 P101.16 R307.1 U1.H10 | length 3904.7
  Top Layer w3.94: U1.H10@3496.06,1226.38 v1(3511.85,1210.59) ; v1(4053.41,1394.87) 4053.41,1398.93 4085.58,1431.1 P101.16@4123.91,1431.1 ; v1(4236.22,1901.57) 4248.03,1913.39 R307.1@4277.56,1913.39
  Signal Layer 3 w3.94: v1(3511.85,1210.59) 3540.05,1238.8 3539.81,1239.04 3539.81,1254.37 3549.21,1263.78 3846.85,1263.78 3977.94,1394.87 v1(4053.41,1394.87) ; v1@4060.01,1394.87 4095.22,1394.87 4216.54,1516.18 4216.54,1881.89 v1(4236.22,1901.57)
  Signal Layer 4 w3.94: J102.18@2018.5,2228.43 2021.42,2228.43 2068.58,2181.26 2731.89,2181.26 2806.3,2255.67 4053.19,2255.67 4210.63,2098.23 4210.63,1927.17 v1(4236.22,1901.57) ; J102.18@2021.65,2237.2 J102.18@2027.28,2237.2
